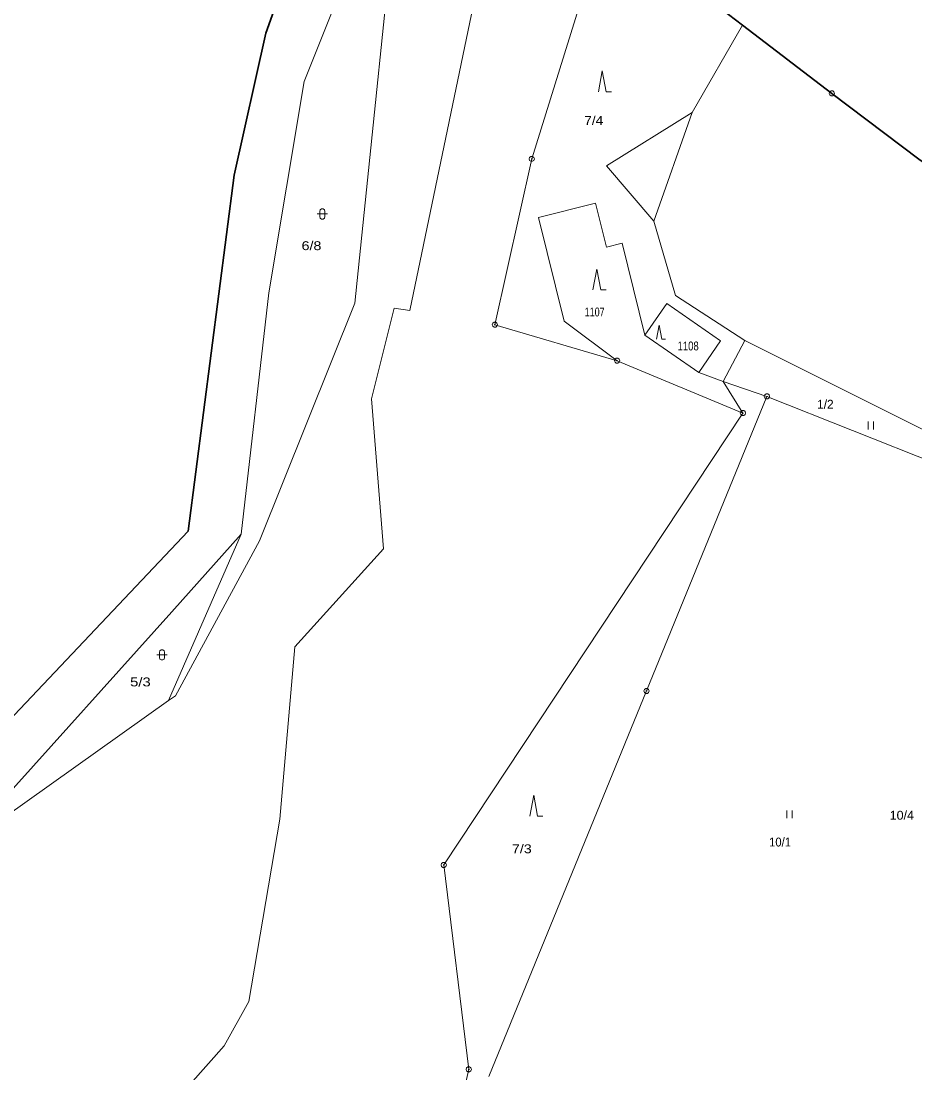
# Model space of a CAD drawing. Extents: x -687390 to -684106, y -954833 to -951648.
# Drawn here: x -686842.5 to -686671.6, y -952098.4 to -951897.2 of the extents above; entities that cross this region are included whole.
import ezdxf
from ezdxf.enums import TextEntityAlignment as Align

# ---------------------------------------------------------------- set-up
doc = ezdxf.new("R2010")
doc.units = 0
doc.header["$LTSCALE"] = 0.68
for name, color, linetype, lineweight in [('1', 7, 'Continuous', 13), ('3', 7, 'Continuous', 13), ('4', 7, 'Continuous', 13), ('7', 7, 'Continuous', 13), ('8', 7, 'Continuous', 13)]:
    doc.layers.add(name, color=color, linetype=linetype, lineweight=lineweight)
doc.layers.add('2', color=7, linetype='Continuous')

msp = doc.modelspace()

# ---------------------------------------------------------------- linework, layer by layer
at = {"layer": '1', "lineweight": 35}
for p, q in [((-686795.73, -951899.53), (-686782.52, -951862.5)), ((-686704.57, -951897.98), (-686687.49, -951911.03)), ((-686801.8, -951926.65), (-686795.73, -951899.53)), ((-686801.8, -951926.65), (-686810.58, -951994.73)), ((-686872.53, -952060.23), (-686810.58, -951994.73))]:
    msp.add_line(p, q, dxfattribs=at)
at = {"layer": '1'}
for p, q in [((-686768.21, -951952.53), (-686751.74, -951873.39)), ((-686714.19, -951914.7), (-686704.57, -951897.98)), ((-686723.24, -951957.27), (-686712.96, -951964.42)), ((-686712.96, -951964.42), (-686708.77, -951958.38)), ((-686704.16, -951958.27), (-686657.92, -951981.4)), ((-686712.96, -951964.42), (-686708.29, -951966.15)), ((-686704.5, -951972.19), (-686708.29, -951966.15)), ((-686699.9, -951969), (-686722.93, -952025.33)), ((-686699.9, -951969), (-686614.7, -952002.92)), ((-686800.46, -951995.35), (-686813.73, -952010.22)), ((-686854.94, -952056.03), (-686813.73, -952010.22)), ((-686753.07, -952099.08), (-686722.93, -952025.33)), ((-686798.99, -952084.75), (-686793.06, -952049.82))]:
    msp.add_line(p, q, dxfattribs=at)
for points in [[(-686769.48, -951861.32), (-686788.38, -951908.76), (-686795.14, -951949.16), (-686800.46, -951995.35)], [(-686769.48, -951861.32), (-686778.74, -951951.18), (-686796.92, -951996.62)], [(-686731.14, -951879.42), (-686744.88, -951923.56), (-686751.93, -951955.28), (-686728.55, -951962.18)], [(-686714.19, -951914.7), (-686730.62, -951924.89), (-686721.52, -951935.44), (-686717.38, -951949.69), (-686704.16, -951958.27), (-686708.29, -951966.15), (-686699.9, -951969)], [(-686704.5, -951972.19), (-686728.55, -951962.18), (-686738.67, -951954.57), (-686743.62, -951934.78), (-686732.67, -951932.04), (-686730.57, -951940.43), (-686727.59, -951939.69), (-686723.24, -951957.27)], [(-686708.77, -951958.38), (-686719.06, -951951.22), (-686723.24, -951957.27)], [(-686768.21, -951952.53), (-686771.19, -951952.13), (-686775.52, -951969.46), (-686773.21, -951998.14), (-686790.18, -952016.87), (-686793.06, -952049.82)], [(-686704.5, -951972.19), (-686761.7, -952058.6), (-686756.92, -952097.72), (-686763.02, -952123.44)], [(-686854.94, -952056.03), (-686814.36, -952027.14), (-686800.46, -951995.35)], [(-686814.36, -952027.14), (-686812.98, -952026.23), (-686796.92, -951996.62)], [(-686798.99, -952084.75), (-686803.69, -952093.23), (-686810.2, -952100.56), (-686819.98, -952104.32), (-686828.22, -952113.25), (-686872.69, -952176.15), (-686879.03, -952189.6)]]:
    msp.add_lwpolyline(points, dxfattribs=at)
at = {"layer": '1', "lineweight": 35}
for points in [[(-686748.65, -951875.48), (-686745.6, -951877.35), (-686738.38, -951878.38), (-686731.14, -951879.42), (-686707.23, -951895.94), (-686704.57, -951897.98)], [(-686687.49, -951911.03), (-686670.84, -951923.59), (-686645.21, -951941.46)]]:
    msp.add_lwpolyline(points, dxfattribs=at)
at = {"layer": '3'}
for p, q in [((-686680.55, -951973.8), (-686680.55, -951975.3)), ((-686679.55, -951975.3), (-686679.55, -951973.8)), ((-686696.08, -952048.17), (-686696.08, -952049.67)), ((-686695.08, -952049.67), (-686695.08, -952048.17))]:
    msp.add_line(p, q, dxfattribs=at)
for points in [[(-686732.14, -951910.72), (-686731.39, -951906.72), (-686730.64, -951910.72), (-686729.64, -951910.72)], [(-686785.93, -951934.09), (-686784.66, -951934.09), (-686783.93, -951934.09)], [(-686733.18, -951948.63), (-686732.43, -951944.63), (-686731.68, -951948.63), (-686730.68, -951948.63)], [(-686721.002, -951958.06), (-686720.5, -951955.38), (-686719.998, -951958.06), (-686719.328, -951958.06)], [(-686816.59, -952018.43), (-686815.32, -952018.43), (-686814.59, -952018.43)], [(-686745.26, -952049.28), (-686744.51, -952045.28), (-686743.76, -952049.28), (-686742.76, -952049.28)]]:
    msp.add_lwpolyline(points, dxfattribs=at)
for points in [[(-686785.43, -951933.59), (-686785.33, -951933.3), (-686785.08, -951933.12), (-686784.77, -951933.12), (-686784.52, -951933.3), (-686784.42, -951933.59), (-686784.42, -951934.59), (-686784.52, -951934.88), (-686784.77, -951935.06), (-686785.08, -951935.06), (-686785.33, -951934.88), (-686785.43, -951934.59)], [(-686816.09, -952017.93), (-686815.99, -952017.64), (-686815.74, -952017.46), (-686815.43, -952017.46), (-686815.18, -952017.64), (-686815.08, -952017.93), (-686815.08, -952018.93), (-686815.18, -952019.22), (-686815.43, -952019.4), (-686815.74, -952019.4), (-686815.99, -952019.22), (-686816.09, -952018.93)]]:
    msp.add_lwpolyline(points, close=True, dxfattribs=at)
at = {"layer": '4'}
msp.add_line((-686721.52, -951935.44), (-686714.19, -951914.7), dxfattribs=at)
at = {"layer": '8'}
for p, q in [((-686687.61, -951911.03), (-686687.37, -951911.03)), ((-686745, -951923.56), (-686744.76, -951923.56)), ((-686752.05, -951955.28), (-686751.81, -951955.28)), ((-686728.67, -951962.18), (-686728.43, -951962.18)), ((-686700.02, -951969), (-686699.78, -951969)), ((-686700.02, -951969), (-686699.78, -951969)), ((-686704.62, -951972.19), (-686704.38, -951972.19)), ((-686723.05, -952025.33), (-686722.81, -952025.33)), ((-686723.05, -952025.33), (-686722.81, -952025.33)), ((-686761.82, -952058.6), (-686761.58, -952058.6)), ((-686757.04, -952097.72), (-686756.8, -952097.72))]:
    msp.add_line(p, q, dxfattribs=at)
for points in [[(-686687.34, -951910.55), (-686687.09, -951910.73), (-686686.99, -951911.02), (-686687.09, -951911.31), (-686687.34, -951911.49), (-686687.65, -951911.49), (-686687.9, -951911.31), (-686688, -951911.02), (-686687.9, -951910.73), (-686687.65, -951910.55)], [(-686744.73, -951923.08), (-686744.48, -951923.26), (-686744.38, -951923.55), (-686744.48, -951923.84), (-686744.73, -951924.02), (-686745.04, -951924.02), (-686745.29, -951923.84), (-686745.39, -951923.55), (-686745.29, -951923.26), (-686745.04, -951923.08)], [(-686751.78, -951954.8), (-686751.53, -951954.98), (-686751.43, -951955.27), (-686751.53, -951955.56), (-686751.78, -951955.74), (-686752.09, -951955.74), (-686752.34, -951955.56), (-686752.44, -951955.27), (-686752.34, -951954.98), (-686752.09, -951954.8)], [(-686728.4, -951961.7), (-686728.15, -951961.88), (-686728.05, -951962.17), (-686728.15, -951962.46), (-686728.4, -951962.64), (-686728.71, -951962.64), (-686728.96, -951962.46), (-686729.06, -951962.17), (-686728.96, -951961.88), (-686728.71, -951961.7)], [(-686699.75, -951968.52), (-686699.5, -951968.7), (-686699.4, -951968.99), (-686699.5, -951969.28), (-686699.75, -951969.46), (-686700.06, -951969.46), (-686700.31, -951969.28), (-686700.41, -951968.99), (-686700.31, -951968.7), (-686700.06, -951968.52)], [(-686699.75, -951968.52), (-686699.5, -951968.7), (-686699.4, -951968.99), (-686699.5, -951969.28), (-686699.75, -951969.46), (-686700.06, -951969.46), (-686700.31, -951969.28), (-686700.41, -951968.99), (-686700.31, -951968.7), (-686700.06, -951968.52)], [(-686704.35, -951971.71), (-686704.1, -951971.89), (-686704, -951972.18), (-686704.1, -951972.47), (-686704.35, -951972.65), (-686704.66, -951972.65), (-686704.91, -951972.47), (-686705.01, -951972.18), (-686704.91, -951971.89), (-686704.66, -951971.71)], [(-686722.78, -952024.85), (-686722.53, -952025.03), (-686722.43, -952025.32), (-686722.53, -952025.61), (-686722.78, -952025.79), (-686723.09, -952025.79), (-686723.34, -952025.61), (-686723.44, -952025.32), (-686723.34, -952025.03), (-686723.09, -952024.85)], [(-686722.78, -952024.85), (-686722.53, -952025.03), (-686722.43, -952025.32), (-686722.53, -952025.61), (-686722.78, -952025.79), (-686723.09, -952025.79), (-686723.34, -952025.61), (-686723.44, -952025.32), (-686723.34, -952025.03), (-686723.09, -952024.85)], [(-686761.55, -952058.12), (-686761.3, -952058.3), (-686761.2, -952058.59), (-686761.3, -952058.88), (-686761.55, -952059.06), (-686761.86, -952059.06), (-686762.11, -952058.88), (-686762.21, -952058.59), (-686762.11, -952058.3), (-686761.86, -952058.12)], [(-686756.77, -952097.24), (-686756.52, -952097.42), (-686756.42, -952097.71), (-686756.52, -952098), (-686756.77, -952098.18), (-686757.08, -952098.18), (-686757.33, -952098), (-686757.43, -952097.71), (-686757.33, -952097.42), (-686757.08, -952097.24)]]:
    msp.add_lwpolyline(points, close=True, dxfattribs=at)

# ---------------------------------------------------------------- texts
at = {"layer": '2'}
for s, width, p in [('7/4', 1.15, (-686734.845, -951917.06)), ('6/8', 1.2, (-686788.896, -951941.01)), ('1107', 0.75, (-686734.745, -951953.69)), ('1108', 0.8, (-686716.995, -951960.19)), ('5/3', 1.25, (-686821.685, -952024.45)), ('10/1', 0.95, (-686699.505, -952055.07)), ('7/3', 1.2, (-686748.675, -952056.36))]:
    msp.add_text(s, height=1.7, dxfattribs=dict(at, width=width)).set_placement(p)
msp.add_text('1/2', height=1.7, dxfattribs=at).set_placement((-686690.315, -951971.34))
at = {"layer": '7', "width": 1.05}
msp.add_text('10/4', height=1.7, dxfattribs=at).set_placement((-686671.796, -952049.95), align=Align.RIGHT)

doc.saveas('drawing.dxf')
